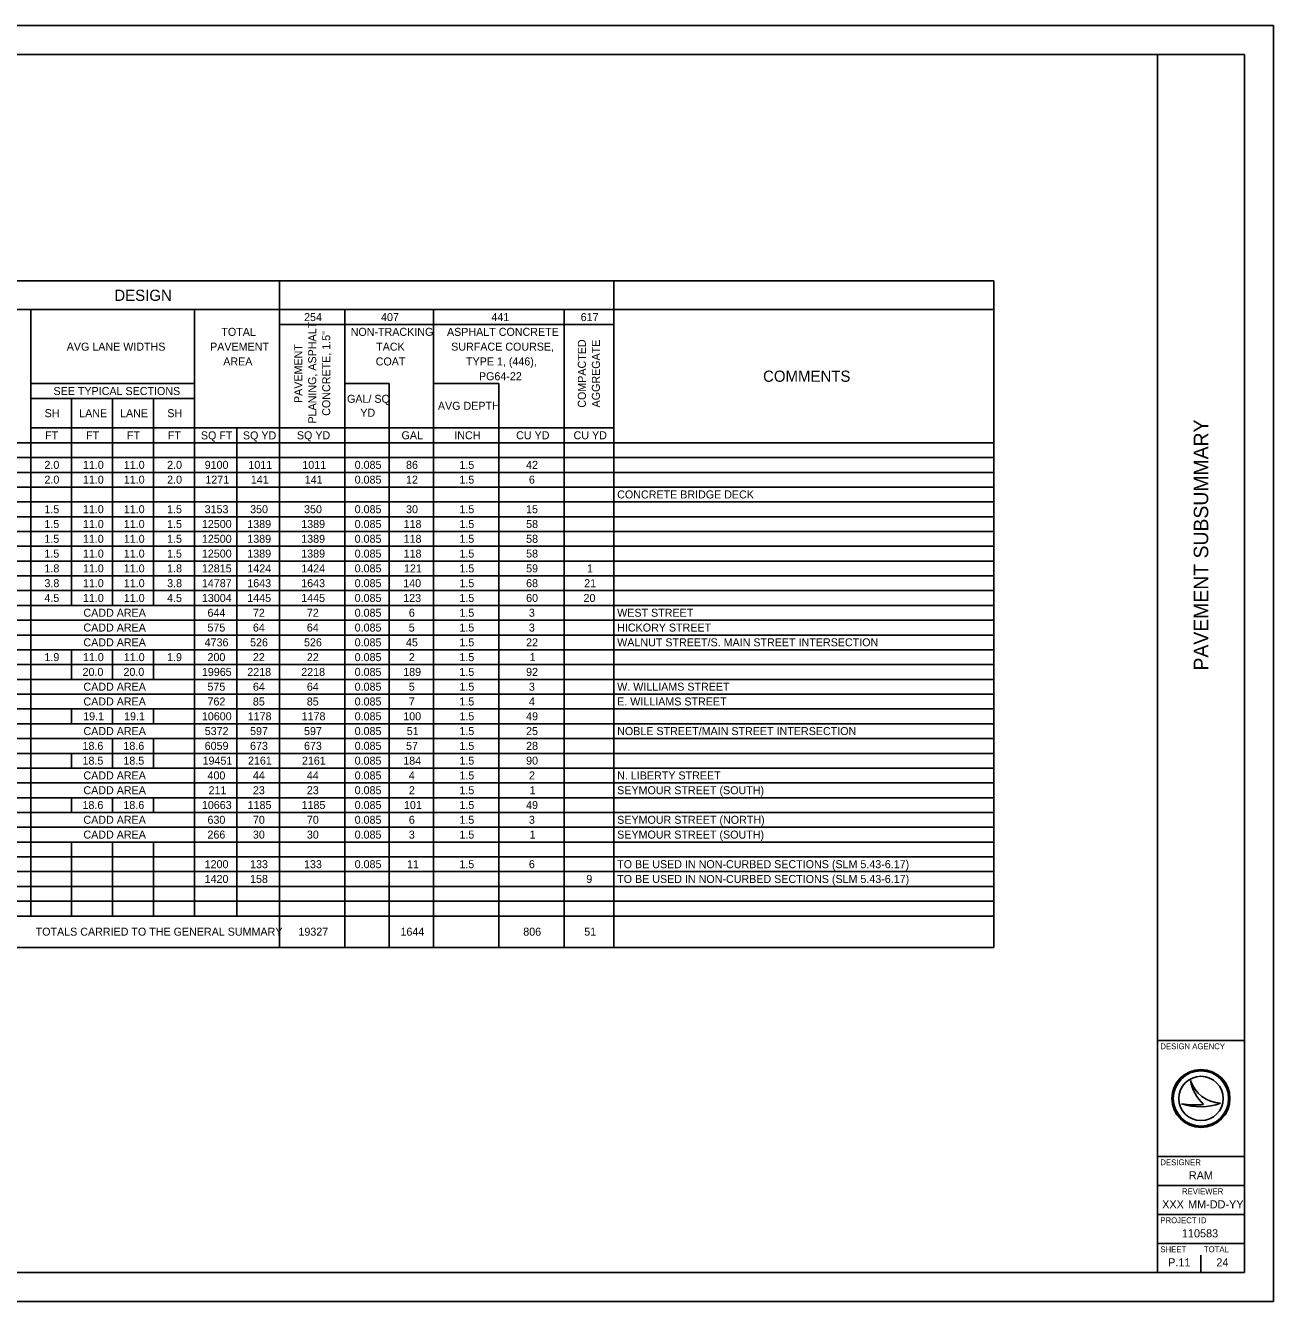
# Model space of a CAD drawing. Extents: x 0 to 34, y 0 to 22.
# Drawn here: x 12.48 to 34, y 0 to 22 of the extents above; entities that cross this region are included whole.
import ezdxf

# ---------------------------------------------------------------- set-up
doc = ezdxf.new("R2010")
doc.units = 0
for name, color, linetype in [('_CIVIL_CONSTRUCTION', 7, 'Continuous'), ('Default', 7, 'Continuous'), ('GE_P_Alignment_100_Bearings', 7, 'Continuous'), ('GE_X_Alignment', 7, 'Continuous')]:
    doc.layers.add(name, color=color, linetype=linetype)

msp = doc.modelspace()

# ---------------------------------------------------------------- linework, layer by layer
at = {"layer": '_CIVIL_CONSTRUCTION'}
for p, q in [((32, 0.5), (32, 21.5)), ((32, 4.5), (33.5, 4.5)), ((32, 2.5), (33.5, 2.5)), ((32, 2), (33.5, 2)), ((32, 1.5), (33.5, 1.5)), ((32, 1), (33.5, 1))]:
    msp.add_line(p, q, dxfattribs=at)
msp.add_lwpolyline([(1.5, 21.5), (33.5, 21.5), (33.5, 0.5), (1.5, 0.5)], close=True, dxfattribs=at)
at = {"layer": 'Default'}
for p, q in [((4.67, 17.596), (29.18, 17.596)), ((16.865, 17.596), (16.865, 6.106)), ((22.625, 17.596), (22.625, 6.106)), ((29.18, 17.596), (29.18, 6.106)), ((4.67, 17.101), (29.18, 17.101)), ((12.575, 17.101), (12.575, 6.646)), ((15.395, 17.101), (15.395, 6.646)), ((17.99, 17.101), (17.99, 6.106)), ((19.52, 17.101), (19.52, 6.106)), ((21.77, 17.101), (21.77, 6.106)), ((16.865, 16.846), (22.625, 16.846)), ((12.575, 15.826), (15.395, 15.826)), ((17.99, 15.826), (18.755, 15.826)), ((18.755, 15.826), (18.755, 6.106)), ((19.52, 15.826), (20.645, 15.826)), ((20.645, 15.826), (20.645, 6.106)), ((12.575, 15.571), (15.395, 15.571)), ((13.28, 15.571), (13.28, 12.001)), ((13.985, 15.571), (13.985, 12.001)), ((14.69, 15.571), (14.69, 12.001)), ((12.575, 15.061), (22.625, 15.061)), ((16.13, 15.061), (16.13, 6.646)), ((4.67, 14.806), (29.18, 14.806)), ((4.67, 14.551), (29.18, 14.551)), ((4.67, 14.296), (29.18, 14.296)), ((4.67, 14.041), (29.18, 14.041)), ((4.67, 13.786), (29.18, 13.786)), ((4.67, 13.531), (29.18, 13.531)), ((4.67, 13.276), (29.18, 13.276)), ((4.67, 13.021), (29.18, 13.021)), ((4.67, 12.766), (29.18, 12.766)), ((4.67, 12.511), (29.18, 12.511)), ((4.67, 12.256), (29.18, 12.256)), ((4.67, 12.001), (29.18, 12.001)), ((4.67, 11.746), (29.18, 11.746)), ((4.67, 11.491), (29.18, 11.491)), ((4.67, 11.236), (29.18, 11.236)), ((13.28, 11.236), (13.28, 10.726)), ((13.985, 11.236), (13.985, 10.726)), ((14.69, 11.236), (14.69, 10.726)), ((4.67, 10.981), (29.18, 10.981)), ((4.67, 10.726), (29.18, 10.726)), ((4.67, 10.471), (29.18, 10.471)), ((4.67, 10.216), (29.18, 10.216)), ((13.28, 10.216), (13.28, 9.961)), ((13.985, 10.216), (13.985, 9.961)), ((14.69, 10.216), (14.69, 9.961)), ((4.67, 9.961), (29.18, 9.961)), ((4.67, 9.706), (29.18, 9.706)), ((13.985, 9.706), (13.985, 9.196)), ((14.69, 9.706), (14.69, 9.196)), ((4.67, 9.451), (29.18, 9.451)), ((13.28, 9.451), (13.28, 9.196)), ((4.67, 9.196), (29.18, 9.196)), ((4.67, 8.941), (29.18, 8.941)), ((4.67, 8.686), (29.18, 8.686)), ((13.28, 8.686), (13.28, 8.431)), ((13.985, 8.686), (13.985, 8.431)), ((14.69, 8.686), (14.69, 8.431)), ((4.67, 8.431), (29.18, 8.431)), ((4.67, 8.176), (29.18, 8.176)), ((4.67, 7.921), (29.18, 7.921)), ((13.28, 7.921), (13.28, 6.646)), ((13.985, 7.921), (13.985, 6.646)), ((14.69, 7.921), (14.69, 6.646)), ((4.67, 7.666), (29.18, 7.666)), ((4.67, 7.411), (29.18, 7.411)), ((4.67, 7.156), (29.18, 7.156)), ((4.67, 6.901), (29.18, 6.901)), ((4.67, 6.646), (29.18, 6.646)), ((4.67, 6.106), (29.18, 6.106))]:
    msp.add_line(p, q, dxfattribs=at)
at = {"layer": 'GE_P_Alignment_100_Bearings'}
for p, q in [((32.567, 3.81), (32.567, 3.81)), ((32.417, 3.41), (32.417, 3.41)), ((32.75, 3.5), (32.75, 3.5)), ((33.087, 3.419), (33.087, 3.419)), ((32.375, 0.675), (32.375, 0.675)), ((32.75, 0.5), (32.75, 0.8))]:
    msp.add_line(p, q, dxfattribs=at)
for radius in [0.5, 0.477, 0.477, 0.382]:
    msp.add_circle((32.75, 3.5), radius, dxfattribs=at)
for centre, radius, start, end in [((33.116, 3.998), 0.58, 198.9257, 198.9319), ((33.347, 3.97), 0.796, 191.6379, 191.6421), ((33.116, 3.998), 0.58, 198.9319, 267.1657), ((33.347, 3.97), 0.796, 191.6421, 226.0947), ((32.739, 4.37), 1.013, 251.4576, 290.0832), ((32.648, 4.654), 1.266, 259.4964, 259.4995), ((32.739, 4.37), 1.013, 251.4527, 251.4576), ((32.648, 4.654), 1.266, 259.4995, 276.6672)]:
    msp.add_arc(centre, radius, start, end, dxfattribs=at)
at = {"layer": 'GE_X_Alignment'}
msp.add_lwpolyline([(0, 0), (34, 0), (34, 22), (0, 22)], close=True, dxfattribs=at)

# ---------------------------------------------------------------- texts
at = {"layer": 'Default'}
for s, height, p in [('DESIGN', 0.1932, (14.016, 17.252)), ('254', 0.138, (17.287, 16.904)), ('407', 0.138, (18.614, 16.904)), ('441', 0.138, (20.516, 16.904)), ('617', 0.138, (22.056, 16.904)), ('TOTAL', 0.138, (15.861, 16.649)), ('NON-TRACKING', 0.138, (18.09, 16.649)), ('ASPHALT CONCRETE', 0.138, (19.751, 16.649)), ('AVG LANE WIDTHS', 0.138, (13.195, 16.394)), ('PAVEMENT', 0.138, (15.667, 16.394)), ('TACK', 0.138, (18.53, 16.394)), ('SURFACE COURSE,', 0.138, (19.823, 16.394)), ('TYPE 1, (446),', 0.138, (20.079, 16.139)), ('AREA', 0.138, (15.893, 16.139)), ('COAT', 0.138, (18.522, 16.139)), ('PG64-22', 0.138, (20.302, 15.884)), ('COMMENTS', 0.1932, (25.2, 15.857)), ('SEE TYPICAL SECTIONS', 0.138, (12.967, 15.629)), ('GAL/ SQ ', 0.138, (18.028, 15.495)), ('AVG DEPTH', 0.138, (19.594, 15.374)), ('SH', 0.138, (12.814, 15.247)), ('LANE', 0.138, (13.41, 15.247)), ('LANE', 0.138, (14.115, 15.247)), ('SH', 0.138, (14.929, 15.247)), ('YD', 0.138, (18.256, 15.254)), ('FT', 0.138, (12.823, 14.864)), ('FT', 0.138, (13.528, 14.864)), ('FT', 0.138, (14.233, 14.864)), ('FT', 0.138, (14.938, 14.864)), ('SQ FT', 0.138, (15.508, 14.864)), ('SQ YD', 0.138, (16.233, 14.864)), ('SQ YD', 0.138, (17.163, 14.866)), ('GAL', 0.138, (18.967, 14.866)), ('INCH', 0.138, (19.877, 14.866)), ('CU YD', 0.138, (20.943, 14.866)), ('CU YD', 0.138, (21.933, 14.866)), ('2.0', 0.138, (12.811, 14.356)), ('11.0', 0.138, (13.474, 14.356)), ('11.0', 0.138, (14.179, 14.356)), ('2.0', 0.138, (14.926, 14.356)), ('9100', 0.138, (15.573, 14.356)), ('1011', 0.138, (16.327, 14.356)), ('1011', 0.138, (17.257, 14.356)), ('0.085', 0.138, (18.159, 14.356)), ('86', 0.138, (19.045, 14.356)), ('1.5', 0.138, (19.965, 14.356)), ('42', 0.138, (21.115, 14.356)), ('2.0', 0.138, (12.811, 14.101)), ('11.0', 0.138, (13.474, 14.101)), ('11.0', 0.138, (14.179, 14.101)), ('2.0', 0.138, (14.926, 14.101)), ('1271', 0.138, (15.585, 14.101)), ('141', 0.138, (16.369, 14.101)), ('141', 0.138, (17.299, 14.101)), ('0.085', 0.138, (18.159, 14.101)), ('12', 0.138, (19.045, 14.101)), ('1.5', 0.138, (19.965, 14.101)), ('6', 0.138, (21.163, 14.101)), ('CONCRETE BRIDGE DECK', 0.138, (22.685, 13.846)), ('1.5', 0.138, (12.81, 13.591)), ('11.0', 0.138, (13.474, 13.591)), ('11.0', 0.138, (14.179, 13.591)), ('1.5', 0.138, (14.925, 13.591)), ('3153', 0.138, (15.573, 13.591)), ('350', 0.138, (16.357, 13.591)), ('350', 0.138, (17.287, 13.591)), ('0.085', 0.138, (18.159, 13.591)), ('30', 0.138, (19.045, 13.591)), ('1.5', 0.138, (19.965, 13.591)), ('15', 0.138, (21.114, 13.591)), ('1.5', 0.138, (12.81, 13.336)), ('11.0', 0.138, (13.474, 13.336)), ('11.0', 0.138, (14.179, 13.336)), ('1.5', 0.138, (14.925, 13.336)), ('12500', 0.138, (15.525, 13.336)), ('1389', 0.138, (16.308, 13.336)), ('1389', 0.138, (17.238, 13.336)), ('0.085', 0.138, (18.159, 13.336)), ('118', 0.138, (19.003, 13.336)), ('1.5', 0.138, (19.965, 13.336)), ('58', 0.138, (21.115, 13.336)), ('1.5', 0.138, (12.81, 13.081)), ('11.0', 0.138, (13.474, 13.081)), ('11.0', 0.138, (14.179, 13.081)), ('1.5', 0.138, (14.925, 13.081)), ('12500', 0.138, (15.525, 13.081)), ('1389', 0.138, (16.308, 13.081)), ('1389', 0.138, (17.238, 13.081)), ('0.085', 0.138, (18.159, 13.081)), ('118', 0.138, (19.003, 13.081)), ('1.5', 0.138, (19.965, 13.081)), ('58', 0.138, (21.115, 13.081)), ('1.5', 0.138, (12.81, 12.826)), ('11.0', 0.138, (13.474, 12.826)), ('11.0', 0.138, (14.179, 12.826)), ('1.5', 0.138, (14.925, 12.826)), ('12500', 0.138, (15.525, 12.826)), ('1389', 0.138, (16.308, 12.826)), ('1389', 0.138, (17.238, 12.826)), ('0.085', 0.138, (18.159, 12.826)), ('118', 0.138, (19.003, 12.826)), ('1.5', 0.138, (19.965, 12.826)), ('58', 0.138, (21.115, 12.826)), ('1.8', 0.138, (12.811, 12.571)), ('11.0', 0.138, (13.474, 12.571)), ('11.0', 0.138, (14.179, 12.571)), ('1.8', 0.138, (14.926, 12.571)), ('12815', 0.138, (15.525, 12.571)), ('1424', 0.138, (16.309, 12.571)), ('1424', 0.138, (17.239, 12.571)), ('0.085', 0.138, (18.159, 12.571)), ('121', 0.138, (19.009, 12.571)), ('1.5', 0.138, (19.965, 12.571)), ('59', 0.138, (21.115, 12.571)), ('1', 0.138, (22.165, 12.571)), ('3.8', 0.138, (12.811, 12.316)), ('11.0', 0.138, (13.474, 12.316)), ('11.0', 0.138, (14.179, 12.316)), ('3.8', 0.138, (14.926, 12.316)), ('14787', 0.138, (15.525, 12.316)), ('1643', 0.138, (16.308, 12.316)), ('1643', 0.138, (17.238, 12.316)), ('0.085', 0.138, (18.159, 12.316)), ('140', 0.138, (18.997, 12.316)), ('1.5', 0.138, (19.965, 12.316)), ('68', 0.138, (21.115, 12.316)), ('21', 0.138, (22.117, 12.316)), ('4.5', 0.138, (12.81, 12.061)), ('11.0', 0.138, (13.474, 12.061)), ('11.0', 0.138, (14.179, 12.061)), ('4.5', 0.138, (14.925, 12.061)), ('13004', 0.138, (15.525, 12.061)), ('1445', 0.138, (16.308, 12.061)), ('1445', 0.138, (17.238, 12.061)), ('0.085', 0.138, (18.159, 12.061)), ('123', 0.138, (18.996, 12.061)), ('1.5', 0.138, (19.965, 12.061)), ('60', 0.138, (21.115, 12.061)), ('20', 0.138, (22.105, 12.061)), ('CADD AREA', 0.138, (13.483, 11.806)), ('644', 0.138, (15.622, 11.806)), ('72', 0.138, (16.405, 11.806)), ('72', 0.138, (17.335, 11.806)), ('0.085', 0.138, (18.159, 11.806)), ('6', 0.138, (19.093, 11.806)), ('1.5', 0.138, (19.965, 11.806)), ('3', 0.138, (21.163, 11.806)), ('WEST STREET', 0.138, (22.685, 11.806)), ('CADD AREA', 0.138, (13.483, 11.551)), ('575', 0.138, (15.621, 11.551)), ('64', 0.138, (16.405, 11.551)), ('64', 0.138, (17.335, 11.551)), ('0.085', 0.138, (18.159, 11.551)), ('5', 0.138, (19.092, 11.551)), ('1.5', 0.138, (19.965, 11.551)), ('3', 0.138, (21.163, 11.551)), ('HICKORY STREET', 0.138, (22.685, 11.551)), ('WALNUT STREET/S. MAIN STREET INTERSECTION', 0.138, (22.685, 11.296)), ('CADD AREA', 0.138, (13.483, 11.296)), ('4736', 0.138, (15.573, 11.296)), ('526', 0.138, (16.356, 11.296)), ('526', 0.138, (17.286, 11.296)), ('0.085', 0.138, (18.159, 11.296)), ('45', 0.138, (19.044, 11.296)), ('1.5', 0.138, (19.965, 11.296)), ('22', 0.138, (21.115, 11.296)), ('1.9', 0.138, (12.811, 11.041)), ('11.0', 0.138, (13.474, 11.041)), ('11.0', 0.138, (14.179, 11.041)), ('1.9', 0.138, (14.926, 11.041)), ('200', 0.138, (15.622, 11.041)), ('22', 0.138, (16.405, 11.041)), ('22', 0.138, (17.335, 11.041)), ('0.085', 0.138, (18.159, 11.041)), ('2', 0.138, (19.094, 11.041)), ('1.5', 0.138, (19.965, 11.041)), ('1', 0.138, (21.175, 11.041)), ('20.0', 0.138, (13.468, 10.786)), ('20.0', 0.138, (14.173, 10.786)), ('19965', 0.138, (15.525, 10.786)), ('2218', 0.138, (16.308, 10.786)), ('2218', 0.138, (17.238, 10.786)), ('0.085', 0.138, (18.159, 10.786)), ('189', 0.138, (18.996, 10.786)), ('1.5', 0.138, (19.965, 10.786)), ('92', 0.138, (21.115, 10.786)), ('CADD AREA', 0.138, (13.483, 10.531)), ('575', 0.138, (15.621, 10.531)), ('64', 0.138, (16.405, 10.531)), ('64', 0.138, (17.335, 10.531)), ('0.085', 0.138, (18.159, 10.531)), ('5', 0.138, (19.092, 10.531)), ('1.5', 0.138, (19.965, 10.531)), ('3', 0.138, (21.163, 10.531)), ('W. WILLIAMS STREET', 0.138, (22.685, 10.531)), ('CADD AREA', 0.138, (13.483, 10.276)), ('762', 0.138, (15.622, 10.276)), ('85', 0.138, (16.404, 10.276)), ('85', 0.138, (17.334, 10.276)), ('0.085', 0.138, (18.159, 10.276)), ('7', 0.138, (19.093, 10.276)), ('1.5', 0.138, (19.965, 10.276)), ('4', 0.138, (21.163, 10.276)), ('E. WILLIAMS STREET', 0.138, (22.685, 10.276)), ('19.1', 0.138, (13.479, 10.021)), ('19.1', 0.138, (14.184, 10.021)), ('10600', 0.138, (15.525, 10.021)), ('1178', 0.138, (16.315, 10.021)), ('1178', 0.138, (17.245, 10.021)), ('0.085', 0.138, (18.159, 10.021)), ('100', 0.138, (18.997, 10.021)), ('1.5', 0.138, (19.965, 10.021)), ('49', 0.138, (21.115, 10.021)), ('CADD AREA', 0.138, (13.483, 9.766)), ('5372', 0.138, (15.574, 9.766)), ('597', 0.138, (16.356, 9.766)), ('597', 0.138, (17.286, 9.766)), ('0.085', 0.138, (18.159, 9.766)), ('51', 0.138, (19.057, 9.766)), ('1.5', 0.138, (19.965, 9.766)), ('25', 0.138, (21.114, 9.766)), ('NOBLE STREET/MAIN STREET INTERSECTION', 0.138, (22.685, 9.766)), ('18.6', 0.138, (13.467, 9.511)), ('18.6', 0.138, (14.172, 9.511)), ('6059', 0.138, (15.573, 9.511)), ('673', 0.138, (16.356, 9.511)), ('673', 0.138, (17.286, 9.511)), ('0.085', 0.138, (18.159, 9.511)), ('57', 0.138, (19.045, 9.511)), ('1.5', 0.138, (19.965, 9.511)), ('28', 0.138, (21.115, 9.511)), ('18.5', 0.138, (13.467, 9.256)), ('18.5', 0.138, (14.172, 9.256)), ('19451', 0.138, (15.537, 9.256)), ('2161', 0.138, (16.32, 9.256)), ('2161', 0.138, (17.25, 9.256)), ('0.085', 0.138, (18.159, 9.256)), ('184', 0.138, (18.997, 9.256)), ('1.5', 0.138, (19.965, 9.256)), ('90', 0.138, (21.115, 9.256)), ('CADD AREA', 0.138, (13.483, 9.001)), ('400', 0.138, (15.622, 9.001)), ('44', 0.138, (16.405, 9.001)), ('44', 0.138, (17.335, 9.001)), ('0.085', 0.138, (18.159, 9.001)), ('4', 0.138, (19.093, 9.001)), ('1.5', 0.138, (19.965, 9.001)), ('2', 0.138, (21.164, 9.001)), ('N. LIBERTY STREET', 0.138, (22.685, 9.001)), ('CADD AREA', 0.138, (13.483, 8.746)), ('211', 0.138, (15.64, 8.746)), ('23', 0.138, (16.405, 8.746)), ('23', 0.138, (17.335, 8.746)), ('0.085', 0.138, (18.159, 8.746)), ('2', 0.138, (19.094, 8.746)), ('1.5', 0.138, (19.965, 8.746)), ('1', 0.138, (21.175, 8.746)), ('SEYMOUR STREET (SOUTH)', 0.138, (22.685, 8.746)), ('18.6', 0.138, (13.467, 8.491)), ('18.6', 0.138, (14.172, 8.491)), ('10663', 0.138, (15.525, 8.491)), ('1185', 0.138, (16.314, 8.491)), ('1185', 0.138, (17.244, 8.491)), ('0.085', 0.138, (18.159, 8.491)), ('101', 0.138, (19.009, 8.491)), ('1.5', 0.138, (19.965, 8.491)), ('49', 0.138, (21.115, 8.491)), ('CADD AREA', 0.138, (13.483, 8.236)), ('630', 0.138, (15.622, 8.236)), ('70', 0.138, (16.405, 8.236)), ('70', 0.138, (17.335, 8.236)), ('0.085', 0.138, (18.159, 8.236)), ('6', 0.138, (19.093, 8.236)), ('1.5', 0.138, (19.965, 8.236)), ('3', 0.138, (21.163, 8.236)), ('SEYMOUR STREET (NORTH)', 0.138, (22.685, 8.236)), ('CADD AREA', 0.138, (13.483, 7.981)), ('266', 0.138, (15.621, 7.981)), ('30', 0.138, (16.405, 7.981)), ('30', 0.138, (17.335, 7.981)), ('0.085', 0.138, (18.159, 7.981)), ('3', 0.138, (19.093, 7.981)), ('1.5', 0.138, (19.965, 7.981)), ('1', 0.138, (21.175, 7.981)), ('SEYMOUR STREET (SOUTH)', 0.138, (22.685, 7.981)), ('1200', 0.138, (15.573, 7.471)), ('133', 0.138, (16.356, 7.471)), ('133', 0.138, (17.286, 7.471)), ('0.085', 0.138, (18.159, 7.471)), ('11', 0.138, (19.063, 7.471)), ('1.5', 0.138, (19.965, 7.471)), ('6', 0.138, (21.163, 7.471)), ('TO BE USED IN NON-CURBED SECTIONS (SLM 5.43-6.17)', 0.138, (22.685, 7.471)), ('1420', 0.138, (15.573, 7.216)), ('158', 0.138, (16.356, 7.216)), ('9', 0.138, (22.153, 7.216)), ('TO BE USED IN NON-CURBED SECTIONS (SLM 5.43-6.17)', 0.138, (22.685, 7.216)), ('TOTALS CARRIED TO THE GENERAL SUMMARY', 0.138, (12.659, 6.307)), ('19327', 0.138, (17.19, 6.307)), ('1644', 0.138, (18.949, 6.307)), ('806', 0.138, (21.066, 6.307)), ('51', 0.138, (22.117, 6.307))]:
    msp.add_text(s, height=height, dxfattribs=at).set_placement(p)
for s, p in [('PLANING, ASPHALT ', (17.496, 15.137)), ('CONCRETE, 1.5"', (17.738, 15.271)), ('PAVEMENT ', (17.255, 15.491)), ('COMPACTED ', (22.145, 15.41)), ('AGGREGATE', (22.387, 15.415))]:
    msp.add_text(s, height=0.138, rotation=90, dxfattribs=at).set_placement(p)
at = {"layer": 'GE_P_Alignment_100_Bearings'}
msp.add_text('PAVEMENT SUBSUMMARY', height=0.25, rotation=90, dxfattribs=at).set_placement((32.875, 10.879))
for s, height, p in [('DESIGN AGENCY', 0.1, (32.05, 4.35)), ('DESIGNER', 0.1, (32.05, 2.35)), ('RAM', 0.14, (32.541, 2.105)), ('REVIEWER', 0.1, (32.422, 1.85)), ('XXX', 0.14, (32.081, 1.605)), ('MM-DD-YY', 0.14, (32.527, 1.605)), ('PROJECT ID', 0.1, (32.05, 1.35)), ('110583', 0.14, (32.421, 1.105)), ('SHEET', 0.1, (32.05, 0.85)), ('TOTAL', 0.1, (32.8, 0.85)), ('P.11', 0.14, (32.184, 0.605)), ('24', 0.14, (33.016, 0.605))]:
    msp.add_text(s, height=height, dxfattribs=at).set_placement(p)

doc.saveas('drawing.dxf')
